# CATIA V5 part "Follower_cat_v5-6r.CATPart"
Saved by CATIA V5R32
Part number: Follower
Bounding box of the stored display mesh (mm): x -9.942 to 9.942, y -9.942 to 9.942, z 0 to 100
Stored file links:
  D:\PROJECTS\Project 2022\CATIA V5 6R 2022\Resources\Tutorial Files\c16_catia_v5_6r2022_tut\Cam Follower mechanism\Follower_cat_v5-6r.CATPart
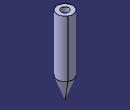
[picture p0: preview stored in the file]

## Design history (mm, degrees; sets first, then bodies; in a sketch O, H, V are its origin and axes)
Body1 (main body)
  Sketch1 on yz-plane, origin (0, 0, 0), H (0, 1, 0), V (0, 0, 1)
    line L1 (0, 0) -> (10, 27.4748)
    point P1 (10, 27.4748)
    line L2 (10, 27.4748) -> (10, 100)
    point P2 (10, 27.4748)
    point P3 (10, 100)
    point P4 (0, 100)
    point P5 (10, 91.3901)
    line L3 (0, 0) -> (0, 100)
    reference intersected line E1 through (0, 0) direction (-1, 0) from xy-plane
    reference intersected line E3 through (0, 0) direction (0, 1) from zx-plane
    line L4 (0, 100) -> (10, 100)
    point P6 (10, 100)
    angle L1 L3 = 20
    distance O P4 = 100
    length L4 = 10
    coincidence: P2 L1, P4 V, P5 L2, P2 P1, E3 P4, P1 L2, P6 L2, P6 P3
    vertical: L2 V, L3 V, E3 V
    horizontal: E1 H, L4 H
    perpendicularity: E1 L2
  Shaft1: profile Sketch1, axis Sketch1.L3, angle 360
  Sketch2 on face of Shaft1 from Sketch1.L4, origin (0, 0, 100), H (1, 0, 0), V (0, 1, 0)
    point P1 (0, 0)
  Hole1: placed by Sketch2, at (0, 0, 100) direction (0, 0, -1), diameter 10, depth 55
